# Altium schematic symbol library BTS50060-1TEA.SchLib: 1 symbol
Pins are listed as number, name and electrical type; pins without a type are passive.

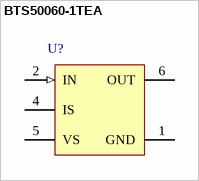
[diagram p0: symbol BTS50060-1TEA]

## BTS50060-1TEA
designator U?
High Current PROFET Smart High-Side Power Switch, 1 Channel, 16.5 A Load Current, -40 to 150 degC, PG-TO252-5-11, Reel, Green; Manufacturer: Infineon; PartNumber: BTS50060-1TEA; Channels: 1; Green: TRUE; Group: Automotive Qualified; Load Current (typ): 16.5 A; Recommended Operating Voltage Max.: 28 V; Recommended Operating Voltage Min.: 4.7 V; RON @ 25degreesC: 6 mOhm; RON(max) @ 150degreesC: 12 mOhm; toff (max): 150 us; ton (max): 130 us
footprint INF-PG-TO252-5_BTF50060_N (DPAK, 5-Leads, Body 6.5x6.12mm, Pitch 1.14mm, IPC Medium Density)
footprint INF-PG-TO252-5_BTF50060_L (DPAK, 5-Leads, Body 6.5x6.12mm, Pitch 1.14mm, IPC High Density)
footprint INF-PG-TO252-5_BTF50060_M (DPAK, 5-Leads, Body 6.5x6.12mm, Pitch 1.14mm, IPC Low Density)
pins: 1 GND (power) "Ground; Ground connection for control chip.", 2 IN (in) "Input; Digital 3.3 V and 5 V compatible logic input; activates power switch if set to HIGH level; Includes internal pull-down resistor RIN.", 4 IS (hiz) "Sense; Provides analog sense current signal and defined fault signal.", 5 VS (power) "Supply Voltage; Positive Supply Voltage for Logic and Power Stage.", 6 OUT (power) "Output; Protected high side power output."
